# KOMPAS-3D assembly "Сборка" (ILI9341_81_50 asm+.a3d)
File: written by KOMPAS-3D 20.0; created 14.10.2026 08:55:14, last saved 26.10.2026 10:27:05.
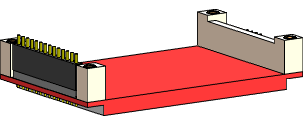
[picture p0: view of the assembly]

Document properties: Полное имя файла: D:\myProjects\Progect_esp32\box_compas\монитор\ILI9341_81_50 asm+.a3d

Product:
- Part/product: Сборка
    Масса: 0.157954
  - Component [assembly]: Сборка  | qty 2  | Масса: 0.0139528; source file: ..\корпус\п-стойка_1 asm.a3d
  - Component [detail]: Деталь  | Масса: 0.123412; source file: ILI9341_81х50.m3d
  - Component [detail]: Деталь  | Масса: 0.00182492; source file: ..\разъемы\pls_14.m3d
  - Component [detail]: Деталь  | Масса: 0.000521406; source file: ..\разъемы\pls_4.m3d
  - Component [detail]: Деталь  | Масса: 0.00428927; source file: ..\разъемы\pbs_14.m3d

Referenced files in D:\myProjects\Progect_esp32\box_compas\монитор\: ILI9341_81х50.m3d
Referenced files in D:\myProjects\Progect_esp32\box_compas\разъемы\: pls_14.m3d, pls_4.m3d, pbs_14.m3d
Referenced files in D:\myProjects\Progect_esp32\box_compas\корпус\: п-стойка_1 asm.a3d
Referenced files in D:\RicWork\Project-EPS32\box_compas\корпус\: п-стойка_1 asm.a3d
